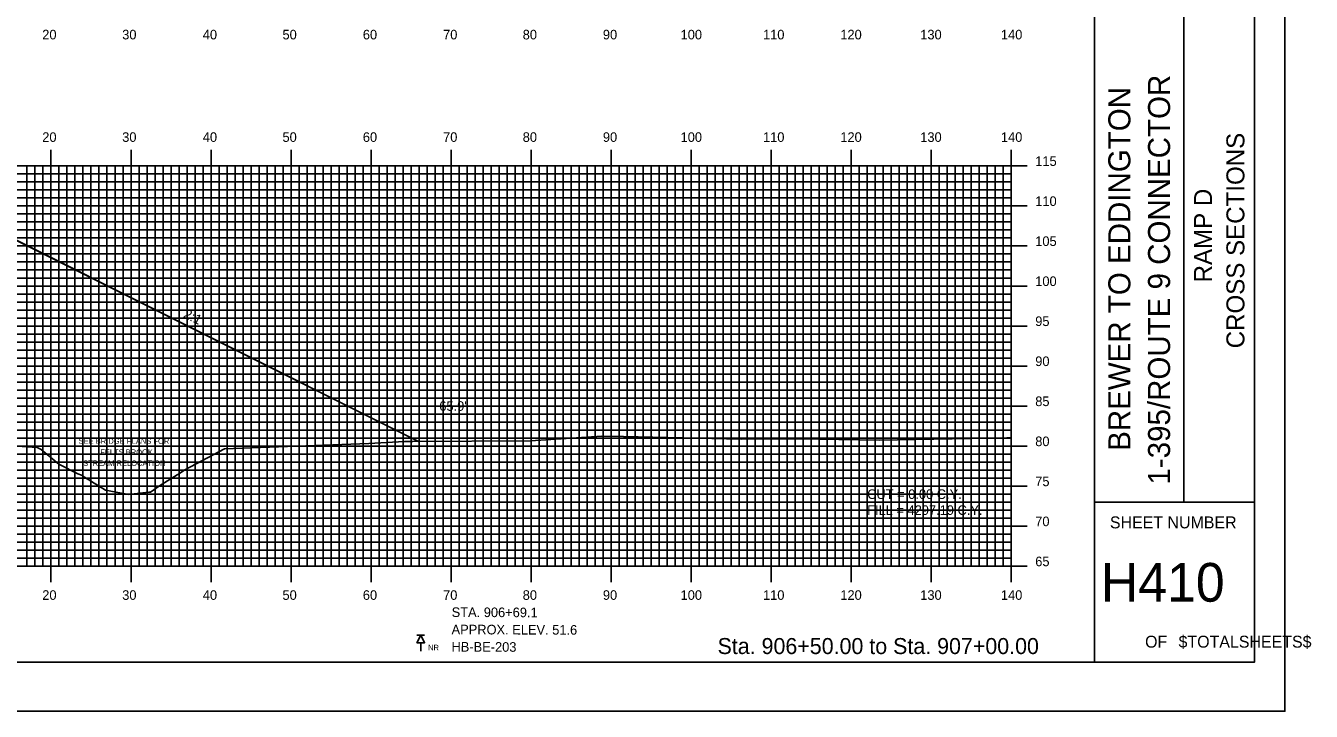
# Model space of a CAD drawing. Extents: x 857897 to 858240, y 364765 to 364985.
# Drawn here: x 858079.7 to 858240.3, y 364765.2 to 364850.8 of the extents above; entities that cross this region are included whole.
import ezdxf

# ---------------------------------------------------------------- set-up
doc = ezdxf.new("R2010")
doc.units = 0
for name, color, linetype in [('ANNOTATION', 7, 'Continuous'), ('BORDER', 7, 'Continuous'), ('BORING - NO REFUSAL', 7, 'Continuous'), ('D_Roadway_Centerline', 7, 'Continuous'), ('D_Roadway_SlopeLines', 7, 'Continuous'), ('D_Text_Standard', 7, 'Continuous'), ('H_V ANNOTATION', 7, 'Continuous'), ('MAJOR', 7, 'Continuous'), ('MINOR', 7, 'Continuous'), ('PLOT BOUNDARY', 7, 'Continuous'), ('S_Roadway_Centerline', 7, 'Continuous')]:
    doc.layers.add(name, color=color, linetype=linetype)

msp = doc.modelspace()

# ---------------------------------------------------------------- linework, layer by layer
at = {"layer": 'BORDER'}
for p, q in [((858213.22, 364771.3), (858213.22, 364981.3)), ((858224.4, 364791.31), (858224.4, 364861.31)), ((858213.22, 364791.31), (858233.22, 364791.31))]:
    msp.add_line(p, q, dxfattribs=at)
msp.add_lwpolyline([(857913.22, 364771.3), (858233.22, 364771.3), (858233.22, 364981.3), (857913.22, 364981.3)], close=True, dxfattribs=at)
at = {"layer": 'BORING - NO REFUSAL'}
for p, q in [((858129.5, 364774.71), (858128.54, 364774.71)), ((858129.02, 364773.75), (858129.02, 364772.69))]:
    msp.add_line(p, q, dxfattribs=at)
msp.add_lwpolyline([(858129.02, 364774.71), (858129.5, 364773.75), (858128.54, 364773.75)], close=True, dxfattribs=at)
at = {"layer": 'D_Roadway_Centerline'}
msp.add_lwpolyline([(857984.22, 364799.38), (858035.61, 364825.07), (858040.82, 364827.68), (858043.82, 364827.74), (858048.82, 364827.84), (858062.82, 364827), (858070.82, 364826.52), (858073.82, 364826.34), (858079.5, 364823.5), (858128.75, 364798.87)], dxfattribs=at)
at = {"layer": 'D_Roadway_SlopeLines'}
msp.add_lwpolyline([(858073.82, 364826.34), (858128.75, 364798.87)], dxfattribs=at)
at = {"layer": 'MAJOR'}
for p, q in [((858082.82, 364835.31), (858082.82, 364833.3)), ((858092.82, 364835.31), (858092.82, 364833.3)), ((858102.82, 364835.31), (858102.82, 364833.3)), ((858112.82, 364835.31), (858112.82, 364833.3)), ((858122.82, 364835.31), (858122.82, 364833.3)), ((858132.82, 364835.31), (858132.82, 364833.3)), ((858142.82, 364835.31), (858142.82, 364833.3)), ((858152.82, 364835.31), (858152.82, 364833.3)), ((858162.82, 364835.31), (858162.82, 364833.3)), ((858172.82, 364835.31), (858172.82, 364833.3)), ((858182.82, 364835.31), (858182.82, 364833.3)), ((858192.82, 364835.31), (858192.82, 364833.3)), ((858202.82, 364835.31), (858202.82, 364833.3)), ((857922.82, 364833.3), (858202.82, 364833.3)), ((857922.82, 364833.3), (858202.82, 364833.3)), ((858082.82, 364783.3), (858082.82, 364833.3)), ((858092.82, 364783.3), (858092.82, 364833.3)), ((858102.82, 364783.3), (858102.82, 364833.3)), ((858112.82, 364783.3), (858112.82, 364833.3)), ((858122.82, 364783.3), (858122.82, 364833.3)), ((858132.82, 364783.3), (858132.82, 364833.3)), ((858142.82, 364783.3), (858142.82, 364833.3)), ((858152.82, 364783.3), (858152.82, 364833.3)), ((858162.82, 364783.3), (858162.82, 364833.3)), ((858172.82, 364783.3), (858172.82, 364833.3)), ((858182.82, 364783.3), (858182.82, 364833.3)), ((858192.82, 364783.3), (858192.82, 364833.3)), ((858204.82, 364833.3), (858200.82, 364833.3)), ((858202.82, 364783.3), (858202.82, 364833.3)), ((858202.82, 364783.3), (858202.82, 364833.3)), ((857922.82, 364828.3), (858202.82, 364828.3)), ((858204.82, 364828.3), (858200.82, 364828.3)), ((857922.82, 364823.3), (858202.82, 364823.3)), ((858204.82, 364823.3), (858200.82, 364823.3)), ((857922.82, 364818.3), (858202.82, 364818.3)), ((858204.82, 364818.3), (858200.82, 364818.3)), ((857922.82, 364813.3), (858202.82, 364813.3)), ((858204.82, 364813.3), (858200.82, 364813.3)), ((857922.82, 364808.3), (858202.82, 364808.3)), ((858204.82, 364808.3), (858200.82, 364808.3)), ((857922.82, 364803.3), (858202.82, 364803.3)), ((858204.82, 364803.3), (858200.82, 364803.3)), ((857922.82, 364798.3), (858202.82, 364798.3)), ((858204.82, 364798.3), (858200.82, 364798.3)), ((857922.82, 364793.3), (858202.82, 364793.3)), ((858204.82, 364793.3), (858200.82, 364793.3)), ((857922.82, 364788.3), (858202.82, 364788.3)), ((858204.82, 364788.3), (858200.82, 364788.3)), ((857922.82, 364783.3), (858202.82, 364783.3)), ((857922.82, 364783.3), (858202.82, 364783.3)), ((858082.82, 364781.3), (858082.82, 364783.3)), ((858092.82, 364781.3), (858092.82, 364783.3)), ((858102.82, 364781.3), (858102.82, 364783.3)), ((858112.82, 364781.3), (858112.82, 364783.3)), ((858122.82, 364781.3), (858122.82, 364783.3)), ((858132.82, 364781.3), (858132.82, 364783.3)), ((858142.82, 364781.3), (858142.82, 364783.3)), ((858152.82, 364781.3), (858152.82, 364783.3)), ((858162.82, 364781.3), (858162.82, 364783.3)), ((858172.82, 364781.3), (858172.82, 364783.3)), ((858182.82, 364781.3), (858182.82, 364783.3)), ((858192.82, 364781.3), (858192.82, 364783.3)), ((858204.82, 364783.3), (858200.82, 364783.3)), ((858202.82, 364781.3), (858202.82, 364783.3))]:
    msp.add_line(p, q, dxfattribs=at)
at = {"layer": 'MINOR'}
for p, q in [((857922.82, 364832.3), (858202.82, 364832.3)), ((858079.82, 364783.3), (858079.82, 364833.3)), ((858080.82, 364783.3), (858080.82, 364833.3)), ((858081.82, 364783.3), (858081.82, 364833.3)), ((858083.82, 364783.3), (858083.82, 364833.3)), ((858084.82, 364783.3), (858084.82, 364833.3)), ((858085.82, 364783.3), (858085.82, 364833.3)), ((858086.82, 364783.3), (858086.82, 364833.3)), ((858087.82, 364783.3), (858087.82, 364833.3)), ((858088.82, 364783.3), (858088.82, 364833.3)), ((858089.82, 364783.3), (858089.82, 364833.3)), ((858090.82, 364783.3), (858090.82, 364833.3)), ((858091.82, 364783.3), (858091.82, 364833.3)), ((858093.82, 364783.3), (858093.82, 364833.3)), ((858094.82, 364783.3), (858094.82, 364833.3)), ((858095.82, 364783.3), (858095.82, 364833.3)), ((858096.82, 364783.3), (858096.82, 364833.3)), ((858097.82, 364783.3), (858097.82, 364833.3)), ((858098.82, 364783.3), (858098.82, 364833.3)), ((858099.82, 364783.3), (858099.82, 364833.3)), ((858100.82, 364783.3), (858100.82, 364833.3)), ((858101.82, 364783.3), (858101.82, 364833.3)), ((858103.82, 364783.3), (858103.82, 364833.3)), ((858104.82, 364783.3), (858104.82, 364833.3)), ((858105.82, 364783.3), (858105.82, 364833.3)), ((858106.82, 364783.3), (858106.82, 364833.3)), ((858107.82, 364783.3), (858107.82, 364833.3)), ((858108.82, 364783.3), (858108.82, 364833.3)), ((858109.82, 364783.3), (858109.82, 364833.3)), ((858110.82, 364783.3), (858110.82, 364833.3)), ((858111.82, 364783.3), (858111.82, 364833.3)), ((858113.82, 364783.3), (858113.82, 364833.3)), ((858114.82, 364783.3), (858114.82, 364833.3)), ((858115.82, 364783.3), (858115.82, 364833.3)), ((858116.82, 364783.3), (858116.82, 364833.3)), ((858117.82, 364783.3), (858117.82, 364833.3)), ((858118.82, 364783.3), (858118.82, 364833.3)), ((858119.82, 364783.3), (858119.82, 364833.3)), ((858120.82, 364783.3), (858120.82, 364833.3)), ((858121.82, 364783.3), (858121.82, 364833.3)), ((858123.82, 364783.3), (858123.82, 364833.3)), ((858124.82, 364783.3), (858124.82, 364833.3)), ((858125.82, 364783.3), (858125.82, 364833.3)), ((858126.82, 364783.3), (858126.82, 364833.3)), ((858127.82, 364783.3), (858127.82, 364833.3)), ((858128.82, 364783.3), (858128.82, 364833.3)), ((858129.82, 364783.3), (858129.82, 364833.3)), ((858130.82, 364783.3), (858130.82, 364833.3)), ((858131.82, 364783.3), (858131.82, 364833.3)), ((858133.82, 364783.3), (858133.82, 364833.3)), ((858134.82, 364783.3), (858134.82, 364833.3)), ((858135.82, 364783.3), (858135.82, 364833.3)), ((858136.82, 364783.3), (858136.82, 364833.3)), ((858137.82, 364783.3), (858137.82, 364833.3)), ((858138.82, 364783.3), (858138.82, 364833.3)), ((858139.82, 364783.3), (858139.82, 364833.3)), ((858140.82, 364783.3), (858140.82, 364833.3)), ((858141.82, 364783.3), (858141.82, 364833.3)), ((858143.82, 364783.3), (858143.82, 364833.3)), ((858144.82, 364783.3), (858144.82, 364833.3)), ((858145.82, 364783.3), (858145.82, 364833.3)), ((858146.82, 364783.3), (858146.82, 364833.3)), ((858147.82, 364783.3), (858147.82, 364833.3)), ((858148.82, 364783.3), (858148.82, 364833.3)), ((858149.82, 364783.3), (858149.82, 364833.3)), ((858150.82, 364783.3), (858150.82, 364833.3)), ((858151.82, 364783.3), (858151.82, 364833.3)), ((858153.82, 364783.3), (858153.82, 364833.3)), ((858154.82, 364783.3), (858154.82, 364833.3)), ((858155.82, 364783.3), (858155.82, 364833.3)), ((858156.82, 364783.3), (858156.82, 364833.3)), ((858157.82, 364783.3), (858157.82, 364833.3)), ((858158.82, 364783.3), (858158.82, 364833.3)), ((858159.82, 364783.3), (858159.82, 364833.3)), ((858160.82, 364783.3), (858160.82, 364833.3)), ((858161.82, 364783.3), (858161.82, 364833.3)), ((858163.82, 364783.3), (858163.82, 364833.3)), ((858164.82, 364783.3), (858164.82, 364833.3)), ((858165.82, 364783.3), (858165.82, 364833.3)), ((858166.82, 364783.3), (858166.82, 364833.3)), ((858167.82, 364783.3), (858167.82, 364833.3)), ((858168.82, 364783.3), (858168.82, 364833.3)), ((858169.82, 364783.3), (858169.82, 364833.3)), ((858170.82, 364783.3), (858170.82, 364833.3)), ((858171.82, 364783.3), (858171.82, 364833.3)), ((858173.82, 364783.3), (858173.82, 364833.3)), ((858174.82, 364783.3), (858174.82, 364833.3)), ((858175.82, 364783.3), (858175.82, 364833.3)), ((858176.82, 364783.3), (858176.82, 364833.3)), ((858177.82, 364783.3), (858177.82, 364833.3)), ((858178.82, 364783.3), (858178.82, 364833.3)), ((858179.82, 364783.3), (858179.82, 364833.3)), ((858180.82, 364783.3), (858180.82, 364833.3)), ((858181.82, 364783.3), (858181.82, 364833.3)), ((858183.82, 364783.3), (858183.82, 364833.3)), ((858184.82, 364783.3), (858184.82, 364833.3)), ((858185.82, 364783.3), (858185.82, 364833.3)), ((858186.82, 364783.3), (858186.82, 364833.3)), ((858187.82, 364783.3), (858187.82, 364833.3)), ((858188.82, 364783.3), (858188.82, 364833.3)), ((858189.82, 364783.3), (858189.82, 364833.3)), ((858190.82, 364783.3), (858190.82, 364833.3)), ((858191.82, 364783.3), (858191.82, 364833.3)), ((858193.82, 364783.3), (858193.82, 364833.3)), ((858194.82, 364783.3), (858194.82, 364833.3)), ((858195.82, 364783.3), (858195.82, 364833.3)), ((858196.82, 364783.3), (858196.82, 364833.3)), ((858197.82, 364783.3), (858197.82, 364833.3)), ((858198.82, 364783.3), (858198.82, 364833.3)), ((858199.82, 364783.3), (858199.82, 364833.3)), ((858200.82, 364783.3), (858200.82, 364833.3)), ((858202.82, 364832.3), (858200.82, 364832.3)), ((858201.82, 364783.3), (858201.82, 364833.3)), ((857922.82, 364831.3), (858202.82, 364831.3)), ((857922.82, 364830.3), (858202.82, 364830.3)), ((858202.82, 364831.3), (858200.82, 364831.3)), ((858202.82, 364830.3), (858200.82, 364830.3)), ((857922.82, 364829.3), (858202.82, 364829.3)), ((858202.82, 364829.3), (858200.82, 364829.3)), ((857922.82, 364827.3), (858202.82, 364827.3)), ((858202.82, 364827.3), (858200.82, 364827.3)), ((857922.82, 364826.3), (858202.82, 364826.3)), ((858202.82, 364826.3), (858200.82, 364826.3)), ((857922.82, 364825.3), (858202.82, 364825.3)), ((857922.82, 364824.3), (858202.82, 364824.3)), ((858202.82, 364825.3), (858200.82, 364825.3)), ((858202.82, 364824.3), (858200.82, 364824.3)), ((857922.82, 364822.3), (858202.82, 364822.3)), ((858202.82, 364822.3), (858200.82, 364822.3)), ((857922.82, 364821.3), (858202.82, 364821.3)), ((858202.82, 364821.3), (858200.82, 364821.3)), ((857922.82, 364820.3), (858202.82, 364820.3)), ((857922.82, 364819.3), (858202.82, 364819.3)), ((858202.82, 364820.3), (858200.82, 364820.3)), ((858202.82, 364819.3), (858200.82, 364819.3)), ((857922.82, 364817.3), (858202.82, 364817.3)), ((857922.82, 364816.3), (858202.82, 364816.3)), ((858202.82, 364817.3), (858200.82, 364817.3)), ((858202.82, 364816.3), (858200.82, 364816.3)), ((857922.82, 364815.3), (858202.82, 364815.3)), ((857922.82, 364814.3), (858202.82, 364814.3)), ((858202.82, 364815.3), (858200.82, 364815.3)), ((858202.82, 364814.3), (858200.82, 364814.3)), ((857922.82, 364812.3), (858202.82, 364812.3)), ((857922.82, 364811.3), (858202.82, 364811.3)), ((858202.82, 364812.3), (858200.82, 364812.3)), ((858202.82, 364811.3), (858200.82, 364811.3)), ((857922.82, 364810.3), (858202.82, 364810.3)), ((858202.82, 364810.3), (858200.82, 364810.3)), ((857922.82, 364809.3), (858202.82, 364809.3)), ((858202.82, 364809.3), (858200.82, 364809.3)), ((857922.82, 364807.3), (858202.82, 364807.3)), ((857922.82, 364806.3), (858202.82, 364806.3)), ((858202.82, 364807.3), (858200.82, 364807.3)), ((858202.82, 364806.3), (858200.82, 364806.3)), ((857922.82, 364805.3), (858202.82, 364805.3)), ((858202.82, 364805.3), (858200.82, 364805.3)), ((857922.82, 364804.3), (858202.82, 364804.3)), ((858202.82, 364804.3), (858200.82, 364804.3)), ((857922.82, 364802.3), (858202.82, 364802.3)), ((858202.82, 364802.3), (858200.82, 364802.3)), ((857922.82, 364801.3), (858202.82, 364801.3)), ((857922.82, 364800.3), (858202.82, 364800.3)), ((858202.82, 364801.3), (858200.82, 364801.3)), ((858202.82, 364800.3), (858200.82, 364800.3)), ((857922.82, 364799.3), (858202.82, 364799.3)), ((858202.82, 364799.3), (858200.82, 364799.3)), ((857922.82, 364797.3), (858202.82, 364797.3)), ((858202.82, 364797.3), (858200.82, 364797.3)), ((857922.82, 364796.3), (858202.82, 364796.3)), ((857922.82, 364795.3), (858202.82, 364795.3)), ((858202.82, 364796.3), (858200.82, 364796.3)), ((858202.82, 364795.3), (858200.82, 364795.3)), ((857922.82, 364794.3), (858202.82, 364794.3)), ((858202.82, 364794.3), (858200.82, 364794.3)), ((857922.82, 364792.3), (858202.82, 364792.3)), ((858202.82, 364792.3), (858200.82, 364792.3)), ((857922.82, 364791.3), (858202.82, 364791.3)), ((857922.82, 364790.3), (858202.82, 364790.3)), ((858202.82, 364791.3), (858200.82, 364791.3)), ((858202.82, 364790.3), (858200.82, 364790.3)), ((857922.82, 364789.3), (858202.82, 364789.3)), ((858202.82, 364789.3), (858200.82, 364789.3)), ((857922.82, 364787.3), (858202.82, 364787.3)), ((858202.82, 364787.3), (858200.82, 364787.3)), ((857922.82, 364786.3), (858202.82, 364786.3)), ((857922.82, 364785.3), (858202.82, 364785.3)), ((858202.82, 364786.3), (858200.82, 364786.3)), ((858202.82, 364785.3), (858200.82, 364785.3)), ((857922.82, 364784.3), (858202.82, 364784.3)), ((858202.82, 364784.3), (858200.82, 364784.3))]:
    msp.add_line(p, q, dxfattribs=at)
at = {"layer": 'PLOT BOUNDARY'}
msp.add_lwpolyline([(857897.03, 364765.18), (858237.03, 364765.18), (858237.03, 364985.18), (857897.03, 364985.18)], close=True, dxfattribs=at)
at = {"layer": 'S_Roadway_Centerline'}
msp.add_lwpolyline([(858073.46, 364798.61), (858081.08, 364798.12), (858081.58, 364797.89), (858083.8, 364796.03), (858086.19, 364794.84), (858086.62, 364794.66), (858087.02, 364794.42), (858089.64, 364792.81), (858092.3, 364792.28), (858092.47, 364792.27), (858095.04, 364792.53), (858095.24, 364792.57), (858096.4, 364793.35), (858098.59, 364794.72), (858098.87, 364794.88), (858099.54, 364795.32), (858104.5, 364797.95), (858122.53, 364798.64), (858126.98, 364798.86), (858128.03, 364798.87), (858142.74, 364798.95), (858151.67, 364799.55), (858154.38, 364799.52), (858169.08, 364799.19), (858176.24, 364799.21), (858186.33, 364799.06), (858202.26, 364799.34), (858202.82, 364799.36)], dxfattribs=at)

# ---------------------------------------------------------------- texts
at = {"layer": 'ANNOTATION'}
msp.add_text('2:1', height=1.2, rotation=333.4349, dxfattribs=at).set_placement((858099.28, 364814.42))
for s, p in [('SEE BRIDGE PLANS FOR', (858086.28, 364798.59)), ('STREAM RELOCATION', (858086.84, 364795.83)), ('FELTS BROOK ', (858088.98, 364797.21))]:
    msp.add_text(s, height=0.68, dxfattribs=at).set_placement(p)
at = {"layer": 'BORDER'}
for s, height, p in [('1-395/ROUTE 9 CONNECTOR', 2.7557, (858222.67, 364793.5)), ('BREWER TO EDDINGTON', 2.7557, (858217.71, 364797.71)), ('CROSS SECTIONS', 2.25, (858231.96, 364810.52)), ('RAMP D', 2.25, (858227.91, 364818.75))]:
    msp.add_text(s, height=height, rotation=90, dxfattribs=at).set_placement(p)
for s, height, p in [('SHEET NUMBER', 1.4905, (858215.15, 364788.03)), ('H410', 4.839, (858214.02, 364778.87)), ('OF', 1.491, (858219.55, 364773.13)), ('$TOTALSHEETS$', 1.4905, (858223.73, 364773.13))]:
    msp.add_text(s, height=height, dxfattribs=at).set_placement(p)
at = {"layer": 'BORING - NO REFUSAL'}
for s, p in [('STA. 906+69.1', (858132.89, 364776.96)), ('APPROX. ELEV. 51.6', (858132.88, 364774.8)), ('HB-BE-203', (858132.87, 364772.64))]:
    msp.add_text(s, height=1.2, rotation=359.8142, dxfattribs=at).set_placement(p)
msp.add_text('NR', height=0.7, dxfattribs=at).set_placement((858129.95, 364772.79))
at = {"layer": 'D_Text_Standard'}
for s, p in [("65.9'", (858131.35, 364802.71)), ('CUT = 0.00 C.Y.', (858184.82, 364791.7)), ('FILL = 4297.19 C.Y.', (858184.82, 364789.71))]:
    msp.add_text(s, height=1.2, dxfattribs=at).set_placement(p)
at = {"layer": 'H_V ANNOTATION'}
for s, height, p in [('20', 1.2, (858081.73, 364849.1)), ('30', 1.2, (858091.72, 364849.1)), ('40', 1.2, (858101.79, 364849.1)), ('50', 1.2, (858111.75, 364849.1)), ('60', 1.2, (858121.79, 364849.1)), ('70', 1.2, (858131.82, 364849.1)), ('80', 1.2, (858141.77, 364849.1)), ('90', 1.2, (858151.79, 364849.1)), ('100', 1.2, (858161.5, 364849.1)), ('110', 1.2, (858171.8, 364849.1)), ('120', 1.2, (858181.46, 364849.1)), ('130', 1.2, (858191.45, 364849.1)), ('140', 1.2, (858201.53, 364849.1)), ('20', 1.2, (858081.73, 364836.3)), ('30', 1.2, (858091.72, 364836.3)), ('40', 1.2, (858101.79, 364836.3)), ('50', 1.2, (858111.75, 364836.3)), ('60', 1.2, (858121.79, 364836.3)), ('70', 1.2, (858131.82, 364836.3)), ('80', 1.2, (858141.77, 364836.3)), ('90', 1.2, (858151.79, 364836.3)), ('100', 1.2, (858161.5, 364836.3)), ('110', 1.2, (858171.8, 364836.3)), ('120', 1.2, (858181.46, 364836.3)), ('130', 1.2, (858191.45, 364836.3)), ('140', 1.2, (858201.53, 364836.3)), ('115', 1.2, (858205.82, 364833.3)), ('110', 1.2, (858205.82, 364828.3)), ('105', 1.2, (858205.82, 364823.3)), ('100', 1.2, (858205.82, 364818.3)), ('95', 1.2, (858205.82, 364813.3)), ('90', 1.2, (858205.82, 364808.3)), ('85', 1.2, (858205.82, 364803.3)), ('80', 1.2, (858205.82, 364798.3)), ('75', 1.2, (858205.82, 364793.3)), ('70', 1.2, (858205.82, 364788.3)), ('65', 1.2, (858205.82, 364783.3)), ('20', 1.2, (858081.73, 364779.1)), ('30', 1.2, (858091.72, 364779.1)), ('40', 1.2, (858101.79, 364779.1)), ('50', 1.2, (858111.75, 364779.1)), ('60', 1.2, (858121.79, 364779.1)), ('70', 1.2, (858131.82, 364779.1)), ('80', 1.2, (858141.77, 364779.1)), ('90', 1.2, (858151.79, 364779.1)), ('100', 1.2, (858161.5, 364779.1)), ('110', 1.2, (858171.8, 364779.1)), ('120', 1.2, (858181.46, 364779.1)), ('130', 1.2, (858191.45, 364779.1)), ('140', 1.2, (858201.53, 364779.1)), ('Sta. 906+50.00 to Sta. 907+00.00', 2.0004, (858166.12, 364772.33))]:
    msp.add_text(s, height=height, dxfattribs=at).set_placement(p)

doc.saveas('drawing.dxf')
